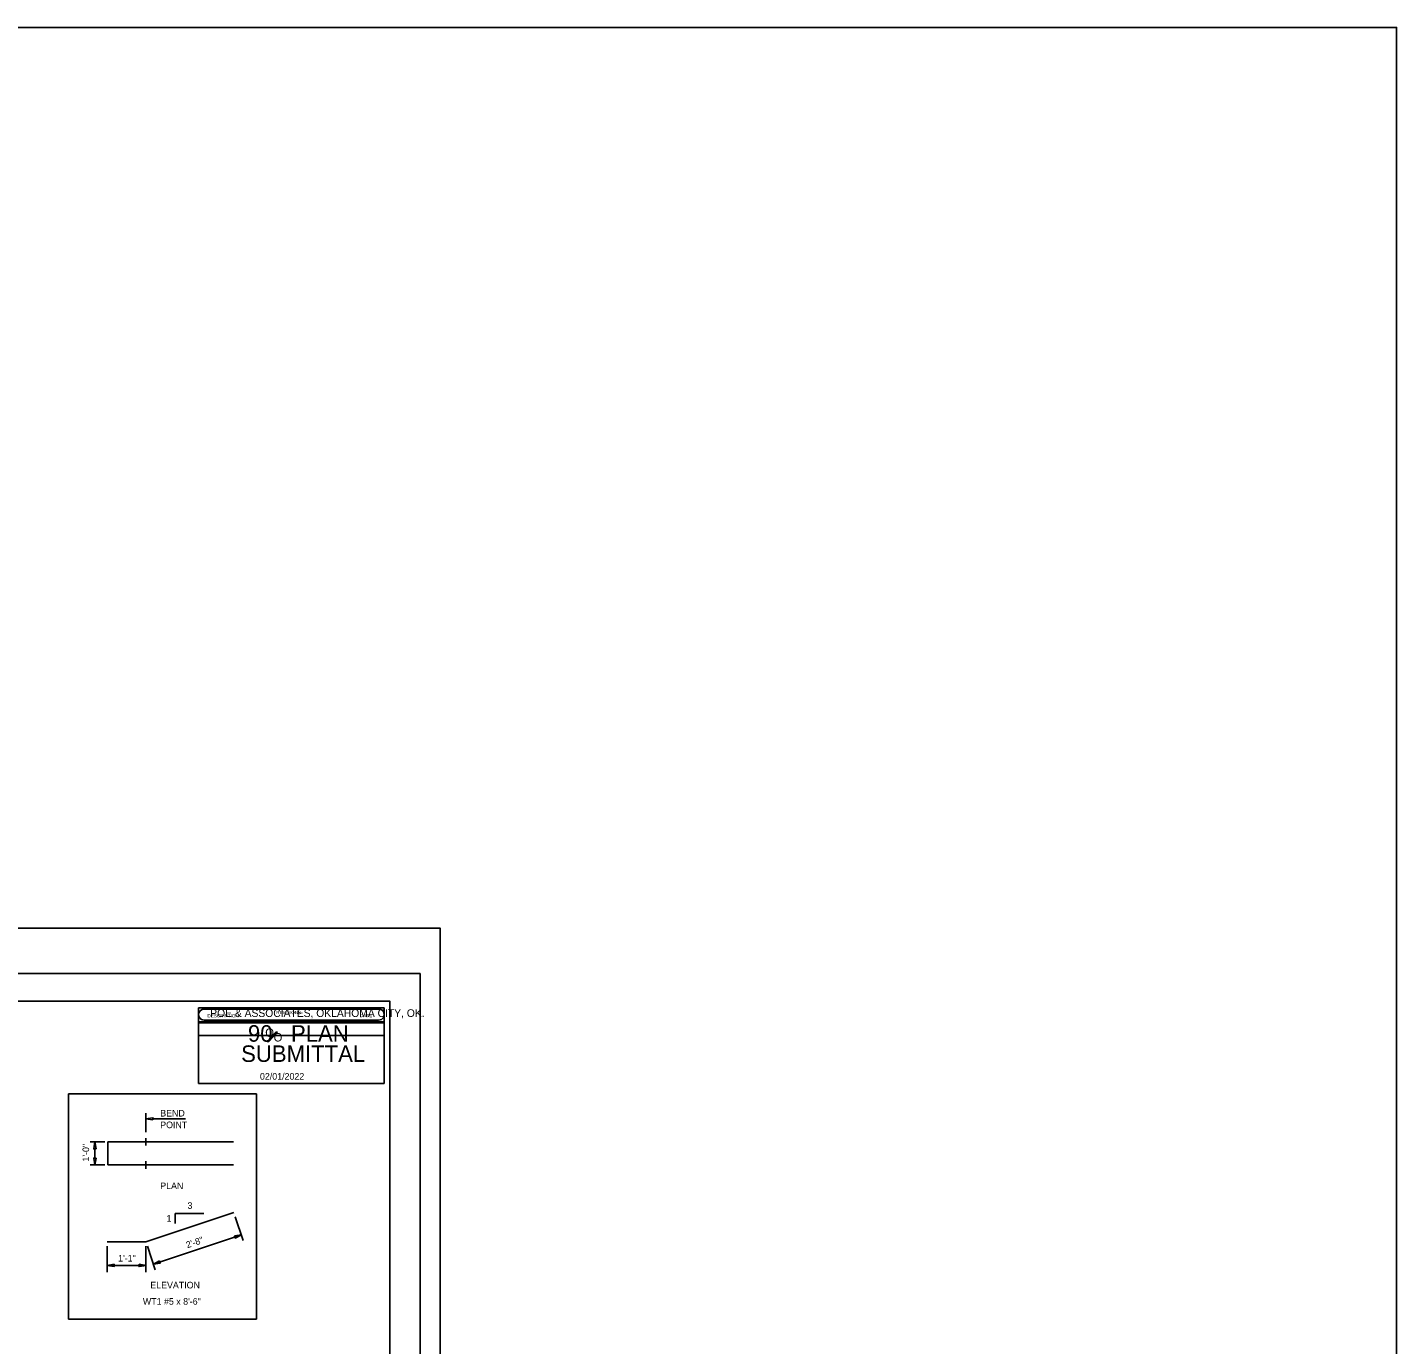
# Model space of a CAD drawing. Extents: x 2146833 to 2153191, y 139029 to 144029.
# Drawn here: x 2147229 to 2147328.4, y 143933.1 to 144028.8 of the extents above; entities that cross this region are included whole.
import ezdxf

# ---------------------------------------------------------------- set-up
doc = ezdxf.new("R2010")
doc.units = 0
for name, color, linetype in [('Default', 7, 'Continuous'), ('PR_Bridge_Rebar', 7, 'Continuous'), ('PR_Dimensions', 7, 'Continuous'), ('S', 7, 'Continuous'), ('SHT_Plot_Shape_Full', 7, 'Continuous'), ('SHT_Plot_Shape_Half', 7, 'Continuous'), ('SHT_Sheet_Border', 7, 'Continuous'), ('SHT_Stamp_90_Submit', 7, 'Continuous'), ('SHT_Stamp_Rev_Block', 7, 'Continuous'), ('T', 7, 'Continuous')]:
    doc.layers.add(name, color=color, linetype=linetype)

# ---------------------------------------------------------------- blocks, each defined once
blk = doc.blocks.new('ARROWHD_11')
at = {"layer": 'Default'}
blk.add_lwpolyline([(0.0261, -0.0045), (0.0261, 0.0043), (-0.0004, -0.0001)], close=True, dxfattribs=at)

msp = doc.modelspace()

# ---------------------------------------------------------------- linework, layer by layer
at = {"layer": 'PR_Bridge_Rebar'}
for p, q in [((2147243.949, 143947.838), (2147234.812, 143947.838)), ((2147234.812, 143947.838), (2147234.812, 143946.171)), ((2147243.949, 143946.171), (2147234.812, 143946.171)), ((2147237.588, 143940.583), (2147243.973, 143942.711)), ((2147234.782, 143940.583), (2147237.588, 143940.583))]:
    msp.add_line(p, q, dxfattribs=at)
at = {"layer": 'PR_Dimensions'}
for p, q in [((2147237.588, 143948.556), (2147237.588, 143949.921)), ((2147238.088, 143949.519), (2147240.458, 143949.519)), ((2147233.533, 143947.838), (2147234.606, 143947.838)), ((2147237.588, 143947.578), (2147237.588, 143948.123)), ((2147233.88, 143947.338), (2147233.88, 143946.671)), ((2147237.588, 143945.895), (2147237.588, 143946.436)), ((2147233.533, 143946.171), (2147234.606, 143946.171)), ((2147239.704, 143942.652), (2147239.704, 143941.908)), ((2147241.78, 143942.652), (2147239.704, 143942.652)), ((2147244.648, 143940.686), (2147244.074, 143942.409)), ((2147244.512, 143941.093), (2147238.128, 143938.965)), ((2147234.782, 143938.377), (2147234.782, 143940.265)), ((2147237.588, 143938.377), (2147237.588, 143940.265)), ((2147238.263, 143938.557), (2147237.689, 143940.281)), ((2147237.588, 143938.877), (2147234.782, 143938.877))]:
    msp.add_line(p, q, dxfattribs=at)
for points in [[(2147231.973, 143951.322), (2147245.608, 143951.322), (2147245.608, 143934.98), (2147231.973, 143934.98)], [(2147238.088, 143949.436), (2147238.088, 143949.603), (2147237.588, 143949.519)], [(2147233.964, 143947.338), (2147233.797, 143947.338), (2147233.88, 143947.838)], [(2147233.964, 143946.671), (2147233.797, 143946.671), (2147233.88, 143946.171)]]:
    msp.add_lwpolyline(points, close=True, dxfattribs=at)
at = {"layer": 'S'}
msp.add_lwpolyline([(2146832.951, 143804.8), (2147328.383, 143804.8), (2147328.383, 144028.754), (2146832.951, 144028.754)], close=True, dxfattribs=at)
at = {"layer": 'SHT_Plot_Shape_Full'}
msp.add_lwpolyline([(2147114.94, 143963.364), (2147258.94, 143963.364), (2147258.94, 143867.364), (2147114.94, 143867.364)], close=True, dxfattribs=at)
at = {"layer": 'SHT_Plot_Shape_Half'}
msp.add_lwpolyline([(2147121.49, 143960.064), (2147257.49, 143960.064), (2147257.49, 143872.064), (2147121.49, 143872.064)], close=True, dxfattribs=at)
at = {"layer": 'SHT_Sheet_Border'}
msp.add_lwpolyline([(2147255.29, 143874.064), (2147129.29, 143874.064), (2147129.29, 143958.064), (2147255.29, 143958.064)], close=True, dxfattribs=at)
at = {"layer": 'SHT_Stamp_90_Submit'}
for p, q in [((2147241.813, 143957.485), (2147254.477, 143957.485)), ((2147241.413, 143956.485), (2147254.877, 143956.485)), ((2147241.413, 143952.088), (2147241.413, 143956.485)), ((2147241.813, 143956.685), (2147254.477, 143956.685)), ((2147254.877, 143952.088), (2147254.877, 143956.485)), ((2147246.386, 143955.132), (2147247.008, 143955.822)), ((2147246.457, 143955.132), (2147247.079, 143955.822)), ((2147246.477, 143955.132), (2147247.099, 143955.822)), ((2147246.508, 143955.132), (2147247.13, 143955.822)), ((2147247.008, 143955.822), (2147247.13, 143955.822)), ((2147246.386, 143955.132), (2147246.508, 143955.132)), ((2147241.413, 143952.088), (2147254.877, 143952.088))]:
    msp.add_line(p, q, dxfattribs=at)
for centre, start, end in [((2147241.814, 143957.086), 89.99522, 270), ((2147254.478, 143957.086), 270, 90.00478)]:
    msp.add_arc(centre, 0.4, start, end, dxfattribs=at)
at = {"layer": 'SHT_Stamp_Rev_Block'}
for p, q in [((2147254.877, 143957.568), (2147241.413, 143957.568)), ((2147241.413, 143955.568), (2147241.413, 143957.568)), ((2147254.477, 143957.568), (2147241.814, 143957.568)), ((2147254.877, 143955.568), (2147254.877, 143957.568)), ((2147254.877, 143956.568), (2147241.413, 143956.568)), ((2147254.877, 143955.568), (2147241.413, 143955.568))]:
    msp.add_line(p, q, dxfattribs=at)

# ---------------------------------------------------------------- block references
at = {"layer": 'PR_Dimensions'}
for p, xscale, yscale, rotation in [((2147244.512, 143941.093), 18.89760000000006, 18.89760000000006, -161.5650515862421), ((2147237.588, 143938.877), 18.897599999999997, 18.897599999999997, 180), ((2147238.135, 143938.966), 18.89760000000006, -18.897599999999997, 18.434948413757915)]:
    msp.add_blockref('ARROWHD_11', p, dxfattribs=dict(at, xscale=xscale, yscale=yscale, rotation=rotation))
at = {"layer": 'PR_Dimensions', "xscale": 18.897599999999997, "yscale": -18.897599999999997}
msp.add_blockref('ARROWHD_11', (2147234.782, 143938.877), dxfattribs=at)

# ---------------------------------------------------------------- texts
at = {"layer": 'SHT_Stamp_90_Submit'}
for s, height, p in [('POE & ASSOCIATES, OKLAHOMA CITY, OK.', 0.56, (2147242.253, 143956.914)), ('90   PLAN', 1.2, (2147244.994, 143955.117)), ('O', 0.612, (2147246.248, 143955.471)), ('O', 0.612, (2147246.856, 143955.134)), ('SUBMITTAL', 1.2, (2147244.498, 143953.65)), ('02/01/2022', 0.48, (2147245.865, 143952.361))]:
    msp.add_text(s, height=height, dxfattribs=at).set_placement(p)
at = {"layer": 'SHT_Stamp_Rev_Block'}
for s, p in [('REVISIONS', (2147247.046, 143957.118)), ('DESCRIPTION', (2147242.052, 143956.881)), ('DATE', (2147253.131, 143956.898))]:
    msp.add_text(s, height=0.24, dxfattribs=at).set_placement(p)
at = {"layer": 'T'}
for s, p in [('BEND', (2147238.624, 143949.687)), ('POINT', (2147238.624, 143948.84)), ('PLAN', (2147238.624, 143944.416)), ('3', (2147240.604, 143942.982)), ('1', (2147239.085, 143942.055)), ('1\'-1"', (2147235.566, 143939.161)), ('ELEVATION', (2147237.903, 143937.207)), ('WT1 #5 x 8\'-6"', (2147237.364, 143936.022))]:
    msp.add_text(s, height=0.48, dxfattribs=at).set_placement(p)
for s, rotation, p in [('1\'-0"', 90, (2147233.462, 143946.417)), ('2\'-8"', 18.43495, (2147240.588, 143940.119))]:
    msp.add_text(s, height=0.48, rotation=rotation, dxfattribs=at).set_placement(p)

doc.saveas('drawing.dxf')
